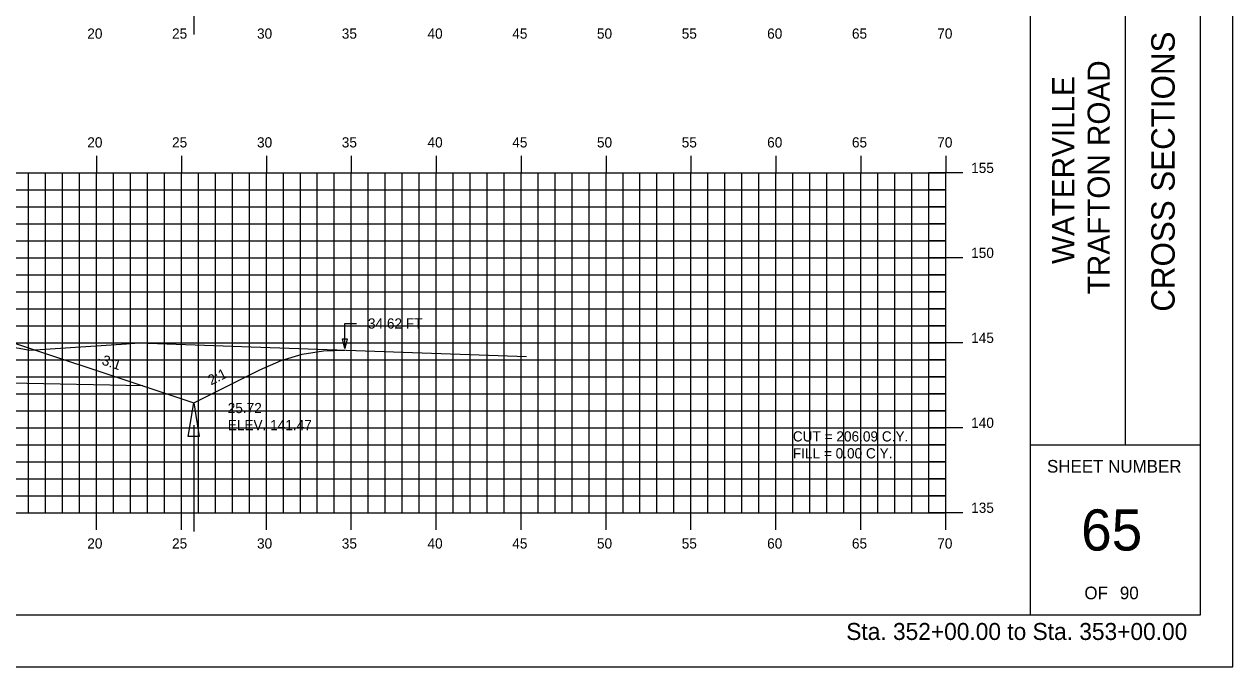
# Model space of a CAD drawing. Extents: x 1144972 to 1145142, y 608981 to 609091.
# Drawn here: x 1145071.1 to 1145142.3, y 608981.3 to 609019.1 of the extents above; entities that cross this region are included whole.
import ezdxf

# ---------------------------------------------------------------- set-up
doc = ezdxf.new("R2010")
doc.units = 0
for name, color, linetype in [('ANNOTATION', 7, 'Continuous'), ('BORDER', 7, 'Continuous'), ('D_Drainage_Ditch_Line', 7, 'Continuous'), ('D_Roadway_SlopeLines', 7, 'Continuous'), ('D_Roadway_SubGrade', 7, 'Continuous'), ('D_Text_Standard', 7, 'Continuous'), ('H_V ANNOTATION', 7, 'Continuous'), ('HIGHWAY_TITLE', 7, 'Continuous'), ('MAJOR', 7, 'Continuous'), ('MINOR', 7, 'Continuous'), ('PLOT BOUNDARY', 7, 'Continuous'), ('S_Roadway_Centerline', 7, 'Continuous')]:
    doc.layers.add(name, color=color, linetype=linetype)

msp = doc.modelspace()

# ---------------------------------------------------------------- linework, layer by layer
msp.add_lwpolyline([(1145017.48, 609001.649), (1145018.73, 609001.566), (1145019.98, 609001.328), (1145021.23, 609000.935), (1145022.48, 609000.387), (1145029.651, 608996.802), (1145032.651, 608997.802), (1145040.374, 609000.376), (1145040.375, 609000.376), (1145044.375, 609000.536), (1145055.375, 609000.756), (1145066.375, 609000.536), (1145070.375, 609000.376), (1145078.099, 608997.802), (1145081.099, 608996.802), (1145084.992, 608998.748), (1145086.242, 608999.29), (1145087.492, 608999.664), (1145088.742, 608999.87), (1145089.992, 608999.91)])
at = {"layer": 'BORDER'}
for p, q in [((1145130.376, 608984.335), (1145130.376, 609089.335)), ((1145135.967, 608994.338), (1145135.967, 609029.338)), ((1145130.376, 608994.338), (1145140.376, 608994.338))]:
    msp.add_line(p, q, dxfattribs=at)
msp.add_lwpolyline([(1144980.376, 608984.335), (1145140.376, 608984.335), (1145140.376, 609089.335), (1144980.376, 609089.335)], close=True, dxfattribs=at)
at = {"layer": 'D_Drainage_Ditch_Line'}
for p, q in [((1145081.099, 609024.727), (1145081.099, 609018.483)), ((1145081.099, 608995.489), (1145081.099, 608989.246))]:
    msp.add_line(p, q, dxfattribs=at)
msp.add_lwpolyline([(1145081.427, 608994.833), (1145080.771, 608994.833), (1145081.099, 608996.802)], close=True, dxfattribs=at)
at = {"layer": 'D_Roadway_SlopeLines'}
for points in [[(1145081.099, 608996.802), (1145084.992, 608998.748), (1145086.242, 608999.29), (1145087.492, 608999.664), (1145088.742, 608999.87), (1145089.992, 608999.91)], [(1145078.099, 608997.802), (1145081.099, 608996.802)]]:
    msp.add_lwpolyline(points, dxfattribs=at)
at = {"layer": 'D_Roadway_SubGrade'}
msp.add_lwpolyline([(1145066.375, 609000.119), (1145066.375, 609000.286), (1145070.375, 609000.126), (1145070.375, 609000.376), (1145070.376, 609000.376), (1145078.099, 608997.802), (1145066.375, 608998.036)], close=True, dxfattribs=at)
at = {"layer": 'D_Text_Standard'}
msp.add_lwpolyline([(1145089.992, 608999.998), (1145089.996, 609001.48), (1145090.676, 609001.48)], dxfattribs=at)
msp.add_lwpolyline([(1145089.992, 608999.998), (1145089.848, 609000.581), (1145090.139, 609000.58)], close=True, dxfattribs=at)
at = {"layer": 'MAJOR'}
for p, q in [((1145075.375, 609011.337), (1145075.375, 609010.335)), ((1145080.375, 609011.337), (1145080.375, 609010.335)), ((1145085.375, 609011.337), (1145085.375, 609010.335)), ((1145090.375, 609011.337), (1145090.375, 609010.335)), ((1145095.375, 609011.337), (1145095.375, 609010.335)), ((1145100.375, 609011.337), (1145100.375, 609010.335)), ((1145105.375, 609011.337), (1145105.375, 609010.335)), ((1145110.375, 609011.337), (1145110.375, 609010.335)), ((1145115.375, 609011.337), (1145115.375, 609010.335)), ((1145120.375, 609011.337), (1145120.375, 609010.335)), ((1145125.375, 609011.337), (1145125.375, 609010.335)), ((1144985.375, 609010.335), (1145125.375, 609010.335)), ((1144985.375, 609010.335), (1145125.375, 609010.335)), ((1145075.375, 608990.335), (1145075.375, 609010.335)), ((1145080.375, 608990.335), (1145080.375, 609010.335)), ((1145085.375, 608990.335), (1145085.375, 609010.335)), ((1145090.375, 608990.335), (1145090.375, 609010.335)), ((1145095.375, 608990.335), (1145095.375, 609010.335)), ((1145100.375, 608990.335), (1145100.375, 609010.335)), ((1145105.375, 608990.335), (1145105.375, 609010.335)), ((1145110.375, 608990.335), (1145110.375, 609010.335)), ((1145115.375, 608990.335), (1145115.375, 609010.335)), ((1145120.375, 608990.335), (1145120.375, 609010.335)), ((1145126.377, 609010.335), (1145124.373, 609010.335)), ((1145125.375, 608990.335), (1145125.375, 609010.335)), ((1145125.375, 608990.335), (1145125.375, 609010.335)), ((1144985.375, 609005.335), (1145125.375, 609005.335)), ((1145126.377, 609005.335), (1145124.373, 609005.335)), ((1144985.375, 609000.335), (1145125.375, 609000.335)), ((1145126.377, 609000.335), (1145124.373, 609000.335)), ((1144985.375, 608995.335), (1145125.375, 608995.335)), ((1145126.377, 608995.335), (1145124.373, 608995.335)), ((1144985.375, 608990.335), (1145125.375, 608990.335)), ((1144985.375, 608990.335), (1145125.375, 608990.335)), ((1145075.375, 608989.333), (1145075.375, 608990.335)), ((1145080.375, 608989.333), (1145080.375, 608990.335)), ((1145085.375, 608989.333), (1145085.375, 608990.335)), ((1145090.375, 608989.333), (1145090.375, 608990.335)), ((1145095.375, 608989.333), (1145095.375, 608990.335)), ((1145100.375, 608989.333), (1145100.375, 608990.335)), ((1145105.375, 608989.333), (1145105.375, 608990.335)), ((1145110.375, 608989.333), (1145110.375, 608990.335)), ((1145115.375, 608989.333), (1145115.375, 608990.335)), ((1145120.375, 608989.333), (1145120.375, 608990.335)), ((1145126.377, 608990.335), (1145124.373, 608990.335)), ((1145125.375, 608989.333), (1145125.375, 608990.335))]:
    msp.add_line(p, q, dxfattribs=at)
at = {"layer": 'MINOR'}
for p, q in [((1145071.375, 608990.335), (1145071.375, 609010.335)), ((1145072.375, 608990.335), (1145072.375, 609010.335)), ((1145073.375, 608990.335), (1145073.375, 609010.335)), ((1145074.375, 608990.335), (1145074.375, 609010.335)), ((1145076.375, 608990.335), (1145076.375, 609010.335)), ((1145077.375, 608990.335), (1145077.375, 609010.335)), ((1145078.375, 608990.335), (1145078.375, 609010.335)), ((1145079.375, 608990.335), (1145079.375, 609010.335)), ((1145081.375, 608990.335), (1145081.375, 609010.335)), ((1145082.375, 608990.335), (1145082.375, 609010.335)), ((1145083.375, 608990.335), (1145083.375, 609010.335)), ((1145084.375, 608990.335), (1145084.375, 609010.335)), ((1145086.375, 608990.335), (1145086.375, 609010.335)), ((1145087.375, 608990.335), (1145087.375, 609010.335)), ((1145088.375, 608990.335), (1145088.375, 609010.335)), ((1145089.375, 608990.335), (1145089.375, 609010.335)), ((1145091.375, 608990.335), (1145091.375, 609010.335)), ((1145092.375, 608990.335), (1145092.375, 609010.335)), ((1145093.375, 608990.335), (1145093.375, 609010.335)), ((1145094.375, 608990.335), (1145094.375, 609010.335)), ((1145096.375, 608990.335), (1145096.375, 609010.335)), ((1145097.375, 608990.335), (1145097.375, 609010.335)), ((1145098.375, 608990.335), (1145098.375, 609010.335)), ((1145099.375, 608990.335), (1145099.375, 609010.335)), ((1145101.375, 608990.335), (1145101.375, 609010.335)), ((1145102.375, 608990.335), (1145102.375, 609010.335)), ((1145103.375, 608990.335), (1145103.375, 609010.335)), ((1145104.375, 608990.335), (1145104.375, 609010.335)), ((1145106.375, 608990.335), (1145106.375, 609010.335)), ((1145107.375, 608990.335), (1145107.375, 609010.335)), ((1145108.375, 608990.335), (1145108.375, 609010.335)), ((1145109.375, 608990.335), (1145109.375, 609010.335)), ((1145111.375, 608990.335), (1145111.375, 609010.335)), ((1145112.375, 608990.335), (1145112.375, 609010.335)), ((1145113.375, 608990.335), (1145113.375, 609010.335)), ((1145114.375, 608990.335), (1145114.375, 609010.335)), ((1145116.375, 608990.335), (1145116.375, 609010.335)), ((1145117.375, 608990.335), (1145117.375, 609010.335)), ((1145118.375, 608990.335), (1145118.375, 609010.335)), ((1145119.375, 608990.335), (1145119.375, 609010.335)), ((1145121.375, 608990.335), (1145121.375, 609010.335)), ((1145122.375, 608990.335), (1145122.375, 609010.335)), ((1145123.375, 608990.335), (1145123.375, 609010.335)), ((1145124.375, 608990.335), (1145124.375, 609010.335)), ((1144985.375, 609009.335), (1145125.375, 609009.335)), ((1145125.375, 609009.335), (1145124.373, 609009.335)), ((1144985.375, 609008.335), (1145125.375, 609008.335)), ((1145125.375, 609008.335), (1145124.373, 609008.335)), ((1144985.375, 609007.335), (1145125.375, 609007.335)), ((1145125.375, 609007.335), (1145124.373, 609007.335)), ((1144985.375, 609006.335), (1145125.375, 609006.335)), ((1145125.375, 609006.335), (1145124.373, 609006.335)), ((1144985.375, 609004.335), (1145125.375, 609004.335)), ((1145125.375, 609004.335), (1145124.373, 609004.335)), ((1144985.375, 609003.335), (1145125.375, 609003.335)), ((1145125.375, 609003.335), (1145124.373, 609003.335)), ((1144985.375, 609002.335), (1145125.375, 609002.335)), ((1145125.375, 609002.335), (1145124.373, 609002.335)), ((1144985.375, 609001.335), (1145125.375, 609001.335)), ((1145125.375, 609001.335), (1145124.373, 609001.335)), ((1144985.375, 608999.335), (1145125.375, 608999.335)), ((1145125.375, 608999.335), (1145124.373, 608999.335)), ((1144985.375, 608998.335), (1145125.375, 608998.335)), ((1145125.375, 608998.335), (1145124.373, 608998.335)), ((1144985.375, 608997.335), (1145125.375, 608997.335)), ((1145125.375, 608997.335), (1145124.373, 608997.335)), ((1144985.375, 608996.335), (1145125.375, 608996.335)), ((1145125.375, 608996.335), (1145124.373, 608996.335)), ((1144985.375, 608994.335), (1145125.375, 608994.335)), ((1145125.375, 608994.335), (1145124.373, 608994.335)), ((1144985.375, 608993.335), (1145125.375, 608993.335)), ((1145125.375, 608993.335), (1145124.373, 608993.335)), ((1144985.375, 608992.335), (1145125.375, 608992.335)), ((1145125.375, 608992.335), (1145124.373, 608992.335)), ((1144985.375, 608991.335), (1145125.375, 608991.335)), ((1145125.375, 608991.335), (1145124.373, 608991.335))]:
    msp.add_line(p, q, dxfattribs=at)
at = {"layer": 'PLOT BOUNDARY'}
msp.add_lwpolyline([(1144972.282, 608981.276), (1145142.282, 608981.276), (1145142.282, 609091.276), (1144972.282, 609091.276)], close=True, dxfattribs=at)
at = {"layer": 'S_Roadway_Centerline'}
msp.add_lwpolyline([(1145004.115, 609001.735), (1145005.693, 609001.744), (1145009.155, 609001.689), (1145025.656, 609001.61), (1145031.824, 609000.263), (1145034.049, 608999.793), (1145036.738, 609000.354), (1145037.982, 609000.651), (1145039.938, 609000.901), (1145040.734, 609000.893), (1145048.301, 609001.069), (1145051.97, 609001.089), (1145053.987, 609000.998), (1145063.171, 609000.834), (1145064.043, 609000.749), (1145067.23, 609000.521), (1145070.819, 609000.016), (1145071.439, 608999.914), (1145077.139, 609000.29), (1145077.857, 609000.331), (1145083.938, 609000.124), (1145100.699, 608999.529)], dxfattribs=at)

# ---------------------------------------------------------------- texts
at = {"layer": 'ANNOTATION'}
for s, rotation, p in [('-3:1', 341.56521, (1145075.387, 608999.16)), ('2:1', 26.56505, (1145082.118, 608997.829))]:
    msp.add_text(s, height=0.6, rotation=rotation, dxfattribs=at).set_placement(p)
at = {"layer": 'BORDER'}
msp.add_text('CROSS SECTIONS', height=1.37787, rotation=90, dxfattribs=at).set_placement((1145138.86, 609002.172))
for s, height, p in [('SHEET NUMBER', 0.74527, (1145131.341, 608992.701)), ('65', 2.4194, (1145133.351, 608988.118)), ('OF', 0.7453, (1145133.543, 608985.248)), ('90', 0.7453, (1145135.632, 608985.248))]:
    msp.add_text(s, height=height, dxfattribs=at).set_placement(p)
at = {"layer": 'D_Text_Standard'}
for s, p in [('34.62 FT', (1145091.356, 609001.18)), ('25.72', (1145083.099, 608996.202)), ('ELEV. 141.47', (1145083.099, 608995.2)), ('CUT = 206.09 C.Y.', (1145116.375, 608994.535)), ('FILL = 0.00 C.Y.', (1145116.375, 608993.539))]:
    msp.add_text(s, height=0.6, dxfattribs=at).set_placement(p)
at = {"layer": 'H_V ANNOTATION'}
for s, height, p in [('20', 0.6, (1145074.829, 609018.235)), ('25', 0.6, (1145079.821, 609018.235)), ('30', 0.6, (1145084.824, 609018.235)), ('35', 0.6, (1145089.816, 609018.235)), ('40', 0.6, (1145094.862, 609018.235)), ('45', 0.6, (1145099.854, 609018.235)), ('50', 0.6, (1145104.84, 609018.235)), ('55', 0.6, (1145109.832, 609018.235)), ('60', 0.6, (1145114.862, 609018.235)), ('65', 0.6, (1145119.854, 609018.235)), ('70', 0.6, (1145124.878, 609018.235)), ('20', 0.6, (1145074.829, 609011.835)), ('25', 0.6, (1145079.821, 609011.835)), ('30', 0.6, (1145084.824, 609011.835)), ('35', 0.6, (1145089.816, 609011.835)), ('40', 0.6, (1145094.862, 609011.835)), ('45', 0.6, (1145099.854, 609011.835)), ('50', 0.6, (1145104.84, 609011.835)), ('55', 0.6, (1145109.832, 609011.835)), ('60', 0.6, (1145114.862, 609011.835)), ('65', 0.6, (1145119.854, 609011.835)), ('70', 0.6, (1145124.878, 609011.835)), ('155', 0.6, (1145126.875, 609010.335)), ('150', 0.6, (1145126.875, 609005.335)), ('145', 0.6, (1145126.875, 609000.335)), ('140', 0.6, (1145126.875, 608995.335)), ('135', 0.6, (1145126.875, 608990.335)), ('20', 0.6, (1145074.829, 608988.235)), ('25', 0.6, (1145079.821, 608988.235)), ('30', 0.6, (1145084.824, 608988.235)), ('35', 0.6, (1145089.816, 608988.235)), ('40', 0.6, (1145094.862, 608988.235)), ('45', 0.6, (1145099.854, 608988.235)), ('50', 0.6, (1145104.84, 608988.235)), ('55', 0.6, (1145109.832, 608988.235)), ('60', 0.6, (1145114.862, 608988.235)), ('65', 0.6, (1145119.854, 608988.235)), ('70', 0.6, (1145124.878, 608988.235)), ('Sta. 352+00.00 to Sta. 353+00.00', 1.0002, (1145119.521, 608982.855))]:
    msp.add_text(s, height=height, dxfattribs=at).set_placement(p)
at = {"layer": 'HIGHWAY_TITLE'}
for s, height, p in [('TRAFTON ROAD', 1.30428, (1145135.035, 609003.201)), ('WATERVILLE', 1.3043, (1145132.948, 609004.98))]:
    msp.add_text(s, height=height, rotation=90, dxfattribs=at).set_placement(p)

doc.saveas('drawing.dxf')
